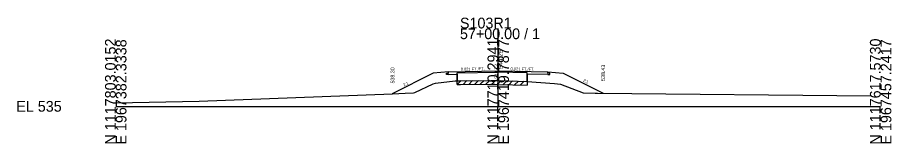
# Model space of a CAD drawing. Extents: x -26 to 203, y -10 to 12018.
# Drawn here: x -25.7 to 202.8, y 2990.3 to 3023.2 of the extents above; entities that cross this region are included whole.
import ezdxf

# ---------------------------------------------------------------- set-up
doc = ezdxf.new("R2010")
doc.units = 0
for name, color, linetype in [('Level 10', 7, 'Continuous'), ('Level 11', 7, 'Continuous'), ('Level 12', 7, 'Continuous'), ('Level 32', 7, 'Continuous'), ('Level 33', 7, 'Continuous'), ('Level 53', 7, 'Continuous'), ('Level 59', 7, 'Continuous'), ('Level 6', 7, 'Continuous'), ('Level 60', 7, 'Continuous'), ('Level 61', 7, 'Continuous'), ('Level 63', 7, 'Continuous'), ('Level 7', 7, 'Continuous')]:
    doc.layers.add(name, color=color, linetype=linetype)

msp = doc.modelspace()

# ---------------------------------------------------------------- linework, layer by layer
at = {"layer": 'Level 11'}
for p, q in [((86.5, 3008.66), (87, 3008.67)), ((86.5, 3008.3), (86.5, 3008.66)), ((87, 3008.31), (86.5, 3008.3)), ((87, 3008.67), (87, 3008.98)), ((113, 3008.67), (113, 3008.98)), ((113.5, 3008.66), (113, 3008.67)), ((113, 3008.31), (113.5, 3008.3)), ((113.5, 3008.3), (113.5, 3008.66))]:
    msp.add_line(p, q, dxfattribs=at)
at = {"layer": 'Level 12'}
for p, q in [((87, 3008.31), (89.3, 3008.36)), ((89.3, 3008.36), (89.3, 3006.69)), ((107.54, 3008.42), (107.54, 3006.52)), ((113, 3008.31), (107.54, 3008.42))]:
    msp.add_line(p, q, dxfattribs=at)
at = {"layer": 'Level 53'}
for p, q in [((89.3, 3008.72), (100, 3008.94)), ((89.3, 3006.69), (89.3, 3008.72)), ((107.54, 3008.78), (100, 3008.94)), ((107.54, 3006.52), (107.54, 3008.78))]:
    msp.add_line(p, q, dxfattribs=at)
at = {"layer": 'Level 59'}
for p, q in [((87, 3008.98), (100, 3009.25)), ((100, 3009.25), (113, 3008.98))]:
    msp.add_line(p, q, dxfattribs=at)
at = {"layer": 'Level 6'}
for p, q in [((87, 3008.98), (83, 3008.65)), ((113, 3008.98), (117, 3008.65))]:
    msp.add_line(p, q, dxfattribs=at)
at = {"layer": 'Level 60'}
for p, q in [((78.21, 3003.57), (83.03, 3005.83)), ((83.03, 3005.83), (83.57, 3006.07)), ((83.57, 3006.07), (88.72, 3006.62)), ((88.72, 3006.62), (89.3, 3006.69)), ((89.3, 3006.69), (90.15, 3006.69)), ((90.15, 3006.69), (98.11, 3006.78)), ((98.11, 3006.78), (99.11, 3006.75)), ((99.11, 3006.75), (100, 3006.73)), ((100, 3006.73), (107.54, 3006.52)), ((107.54, 3006.52), (114.69, 3005.92)), ((114.69, 3005.92), (116.33, 3005.78)), ((116.33, 3005.78), (122.19, 3003.51)), ((21.81, 3001.37), (72.37, 3003.3)), ((72.37, 3003.3), (75.64, 3003.44)), ((75.64, 3003.44), (77.86, 3003.56)), ((77.86, 3003.56), (78.21, 3003.57)), ((122.19, 3003.51), (125.35, 3003.43)), ((125.35, 3003.43), (125.94, 3003.45)), ((125.94, 3003.45), (197.48, 3002.74)), ((0, 3000.93), (21.81, 3001.37))]:
    msp.add_line(p, q, dxfattribs=at)
at = {"layer": 'Level 61'}
for p, q in [((89.3, 3005.69), (90.31, 3006.7)), ((89.3, 3005.69), (89.3, 3006.69)), ((89.3, 3005.69), (90.15, 3005.69)), ((90.15, 3005.69), (98.11, 3005.78)), ((90.8, 3005.7), (91.81, 3006.71)), ((92.3, 3005.72), (93.31, 3006.73)), ((93.8, 3005.73), (94.81, 3006.74)), ((95.3, 3005.75), (96.31, 3006.76)), ((96.8, 3005.76), (97.81, 3006.77)), ((98.11, 3005.78), (99.11, 3005.75)), ((98.3, 3005.77), (99.28, 3006.75)), ((99.11, 3005.75), (100, 3005.73)), ((99.8, 3005.73), (100.77, 3006.71)), ((100, 3005.73), (107.54, 3005.52)), ((101.3, 3005.69), (102.27, 3006.67)), ((102.8, 3005.65), (103.77, 3006.62)), ((104.3, 3005.61), (105.27, 3006.58)), ((105.8, 3005.57), (106.77, 3006.54)), ((107.54, 3006.52), (107.54, 3005.52))]:
    msp.add_line(p, q, dxfattribs=at)
at = {"layer": 'Level 63'}
for p, q in [((100, 3000), (100, 3020.33)), ((0, 3000), (100, 3000)), ((100, 3000), (200, 3000))]:
    msp.add_line(p, q, dxfattribs=at)
at = {"layer": 'Level 7'}
for p, q in [((83, 3008.65), (72.31, 3003.3)), ((117, 3008.65), (127.43, 3003.43))]:
    msp.add_line(p, q, dxfattribs=at)

# ---------------------------------------------------------------- texts
at = {"layer": 'Level 10'}
msp.add_text(' 541.73', height=0.9, rotation=90, dxfattribs=at).set_placement((99.95, 3006.87))
at = {"layer": 'Level 32'}
for s, rotation, p in [('0.021 FT./FT.', 1.1916, (90.21, 3009.3)), ('0.021 FT./FT.', 358.8084, (103.22, 3009.43)), ('2:1', 26.5651, (75.35, 3005.17)), ('2:1', 333.4349, (122.1, 3006.53))]:
    msp.add_text(s, height=0.75, rotation=rotation, dxfattribs=at).set_placement(p)
at = {"layer": 'Level 33'}
for s, p in [('538.30', (72.87, 3005.96)), ('538.43', (127.93, 3006.62))]:
    msp.add_text(s, height=1, rotation=90, dxfattribs=at).set_placement(p)
at = {"layer": 'Level 59'}
msp.add_text(' 544.25', height=1.2, rotation=90, dxfattribs=at).set_placement((101.2, 3009.25))
at = {"layer": 'Level 63'}
for s, p in [('S103R1', (90, 3020.33)), ('57+00.00 / 1', (90, 3017.53)), ('EL 535', (-26, 2998.6))]:
    msp.add_text(s, height=2.8, dxfattribs=at).set_placement(p)
for s, p in [('N 1117803.0152', (0, 2990)), ('E 1967382.3338', (2.8, 2990)), ('N 1117710.2941', (100, 2990)), ('E 1967419.7877', (102.8, 2990)), ('N 1117617.5730', (200, 2990)), ('E 1967457.2417', (202.8, 2990))]:
    msp.add_text(s, height=2.8, rotation=90, dxfattribs=at).set_placement(p)

doc.saveas('drawing.dxf')
